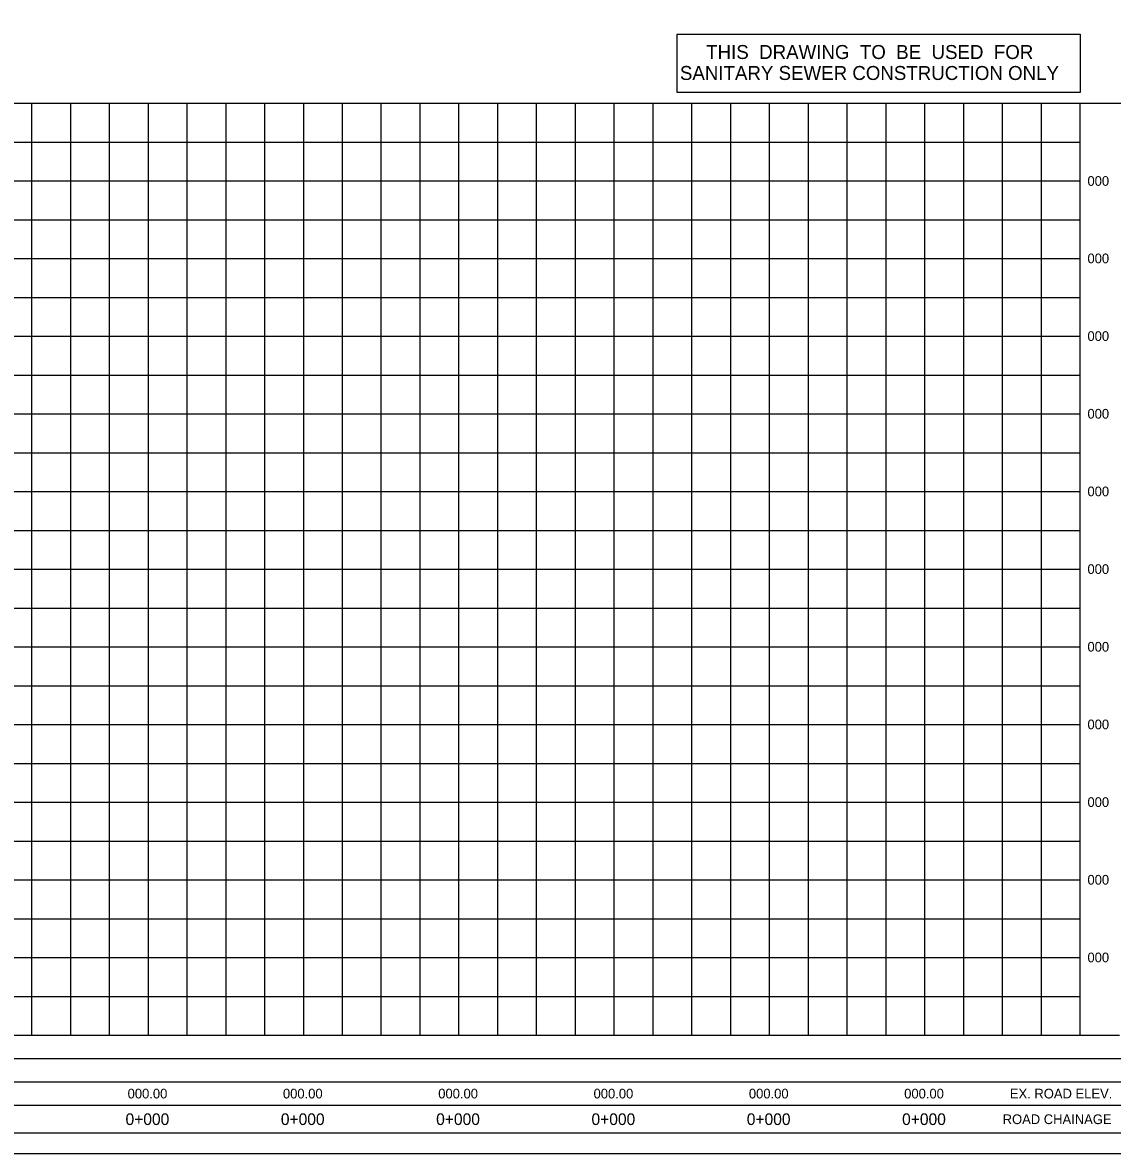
# Model space of a CAD drawing. Extents: x 613360 to 613780, y 4825621 to 4825911.
# Drawn here: x 613569.5 to 613709.9, y 4825620.9 to 4825766.5 of the extents above; entities that cross this region are included whole.
import ezdxf

# ---------------------------------------------------------------- set-up
doc = ezdxf.new("R2010")
doc.units = 0
for name, color, linetype in [('G-ANNO-TEXT', 7, 'Continuous'), ('G-GRID-MAJ', 7, 'Continuous'), ('G-GRID-MIN', 7, 'Continuous'), ('G-TTLB-OTLN', 7, 'Continuous'), ('G-TTLB-OTLN-PB', 7, 'Continuous')]:
    doc.layers.add(name, color=color, linetype=linetype)

msp = doc.modelspace()

# ---------------------------------------------------------------- linework, layer by layer
at = {"layer": 'G-ANNO-TEXT'}
msp.add_lwpolyline([(613653.81, 4825765), (613705.73, 4825765), (613705.73, 4825757.48), (613653.81, 4825757.48)], close=True, dxfattribs=at)
at = {"layer": 'G-GRID-MAJ'}
for p, q in [((613585.73, 4825636.11), (613585.73, 4825756.11)), ((613605.73, 4825636.11), (613605.73, 4825756.11)), ((613625.73, 4825636.11), (613625.73, 4825756.11)), ((613645.73, 4825636.11), (613645.73, 4825756.11)), ((613665.73, 4825636.11), (613665.73, 4825756.11)), ((613685.73, 4825636.11), (613685.73, 4825756.11)), ((613705.73, 4825636.11), (613705.73, 4825756.11)), ((613385.73, 4825746.11), (613705.73, 4825746.11)), ((613385.73, 4825736.11), (613705.73, 4825736.11)), ((613385.73, 4825726.11), (613705.73, 4825726.11)), ((613385.73, 4825716.11), (613705.73, 4825716.11)), ((613385.73, 4825706.11), (613705.73, 4825706.11)), ((613385.73, 4825696.11), (613705.73, 4825696.11)), ((613385.73, 4825686.11), (613705.73, 4825686.11)), ((613385.73, 4825676.11), (613705.73, 4825676.11)), ((613385.73, 4825666.11), (613705.73, 4825666.11)), ((613385.73, 4825656.11), (613705.73, 4825656.11)), ((613385.73, 4825646.11), (613705.73, 4825646.11))]:
    msp.add_line(p, q, dxfattribs=at)
at = {"layer": 'G-GRID-MIN'}
for p, q in [((613570.73, 4825636.11), (613570.73, 4825756.11)), ((613575.73, 4825636.11), (613575.73, 4825756.11)), ((613580.73, 4825636.11), (613580.73, 4825756.11)), ((613590.73, 4825636.11), (613590.73, 4825756.11)), ((613595.73, 4825636.11), (613595.73, 4825756.11)), ((613600.73, 4825636.11), (613600.73, 4825756.11)), ((613610.73, 4825636.11), (613610.73, 4825756.11)), ((613615.73, 4825636.11), (613615.73, 4825756.11)), ((613620.73, 4825636.11), (613620.73, 4825756.11)), ((613630.73, 4825636.11), (613630.73, 4825756.11)), ((613635.73, 4825636.11), (613635.73, 4825756.11)), ((613640.73, 4825636.11), (613640.73, 4825756.11)), ((613650.73, 4825636.11), (613650.73, 4825756.11)), ((613655.73, 4825636.11), (613655.73, 4825756.11)), ((613660.73, 4825636.11), (613660.73, 4825756.11)), ((613670.73, 4825636.11), (613670.73, 4825756.11)), ((613675.73, 4825636.11), (613675.73, 4825756.11)), ((613680.73, 4825636.11), (613680.73, 4825756.11)), ((613690.73, 4825636.11), (613690.73, 4825756.11)), ((613695.73, 4825636.11), (613695.73, 4825756.11)), ((613700.73, 4825636.11), (613700.73, 4825756.11)), ((613385.73, 4825751.11), (613705.73, 4825751.11)), ((613385.73, 4825741.11), (613705.73, 4825741.11)), ((613385.73, 4825731.11), (613705.73, 4825731.11)), ((613385.73, 4825721.11), (613705.73, 4825721.11)), ((613385.73, 4825711.11), (613705.73, 4825711.11)), ((613385.73, 4825701.11), (613705.73, 4825701.11)), ((613385.73, 4825691.11), (613705.73, 4825691.11)), ((613385.73, 4825681.11), (613705.73, 4825681.11)), ((613385.73, 4825671.11), (613705.73, 4825671.11)), ((613385.73, 4825661.11), (613705.73, 4825661.11)), ((613385.73, 4825651.11), (613705.73, 4825651.11)), ((613385.73, 4825641.11), (613705.73, 4825641.11))]:
    msp.add_line(p, q, dxfattribs=at)
at = {"layer": 'G-TTLB-OTLN'}
for p, q in [((613380.09, 4825756.11), (613774.18, 4825756.11)), ((613380.09, 4825636.11), (613710.78, 4825636.11)), ((613380.09, 4825633.11), (613774.18, 4825633.11)), ((613380.09, 4825630.11), (613749.42, 4825630.11)), ((613380.09, 4825627.11), (613749.42, 4825627.11))]:
    msp.add_line(p, q, dxfattribs=at)
msp.add_lwpolyline([(613380.09, 4825892.08), (613774.18, 4825892.08), (613774.18, 4825623.51), (613380.09, 4825623.51)], close=True, dxfattribs=at)
at = {"layer": 'G-TTLB-OTLN-PB'}
msp.add_lwpolyline([(613359.58, 4825620.91), (613780.27, 4825620.91), (613780.27, 4825894.68), (613359.58, 4825894.68)], close=True, dxfattribs=at)

# ---------------------------------------------------------------- texts
at = {"layer": 'G-ANNO-TEXT'}
for s, height, rotation, p in [('THIS  DRAWING  TO  BE  USED  FOR', 1.8, 359.9969, (613657.56, 4825761.81)), ('SANITARY SEWER CONSTRUCTION ONLY', 1.8, 359.9969, (613654.18, 4825759.11)), ('000', 1.25, 360, (613706.66, 4825735.51)), ('000', 1.25, 360, (613706.66, 4825725.51)), ('000', 1.25, 360, (613706.66, 4825715.51)), ('000', 1.25, 360, (613706.66, 4825705.51)), ('000', 1.25, 360, (613706.66, 4825695.51)), ('000', 1.25, 360, (613706.66, 4825685.51)), ('000', 1.25, 360, (613706.66, 4825675.51)), ('000', 1.25, 360, (613706.66, 4825665.51)), ('000', 1.25, 360, (613706.66, 4825655.51)), ('000', 1.25, 360, (613706.66, 4825645.51))]:
    msp.add_text(s, height=height, rotation=rotation, dxfattribs=at).set_placement(p)
for s, height, p in [('000', 1.25, (613706.66, 4825745.48)), ('000.00', 1.25, (613583.06, 4825627.98)), ('000.00', 1.25, (613603.06, 4825627.98)), ('000.00', 1.25, (613623.06, 4825627.98)), ('000.00', 1.25, (613643.06, 4825627.98)), ('000.00', 1.25, (613663.06, 4825627.98)), ('000.00', 1.25, (613683.06, 4825627.98)), ('EX. ROAD ELEV.', 1.25, (613696.67, 4825627.98)), ('0+000', 1.5, (613582.79, 4825624.56)), ('0+000', 1.5, (613602.79, 4825624.56)), ('0+000', 1.5, (613622.79, 4825624.56)), ('0+000', 1.5, (613642.79, 4825624.56)), ('0+000', 1.5, (613662.79, 4825624.56)), ('0+000', 1.5, (613682.79, 4825624.56)), ('ROAD CHAINAGE', 1.25, (613695.74, 4825624.68))]:
    msp.add_text(s, height=height, dxfattribs=at).set_placement(p)

doc.saveas('drawing.dxf')
